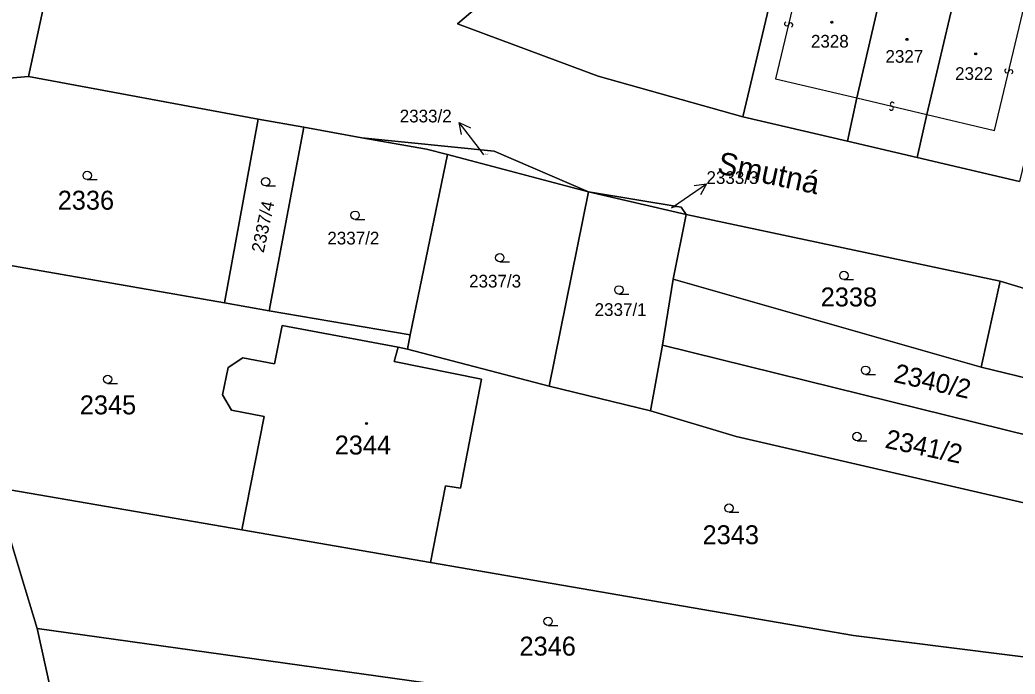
# Model space of a CAD drawing. Extents: x -596024 to -594475, y -1163820 to -1161957.
# Drawn here: x -595927.3 to -595838.1, y -1163093.4 to -1163034.7 of the extents above; entities that cross this region are included whole.
import ezdxf

# ---------------------------------------------------------------- set-up
doc = ezdxf.new("R2010")
doc.units = 0
for name, color, linetype in [('Level 1', 7, 'Continuous'), ('Level 11', 7, 'Continuous'), ('Level 13', 7, 'Continuous'), ('Level 3', 7, 'Continuous'), ('Level 4', 7, 'Continuous'), ('Level 5', 7, 'Continuous'), ('Level 57', 7, 'Continuous'), ('Level 60', 7, 'Continuous')]:
    doc.layers.add(name, color=color, linetype=linetype)

msp = doc.modelspace()

# ---------------------------------------------------------------- linework, layer by layer
at = {"layer": 'Level 1'}
for points in [[(-595857.24, -1163021.24), (-595862.49, -1163043.42)], [(-595862.49, -1163043.42), (-595875.46, -1163039.76), (-595888.08, -1163035.08), (-595884.71, -1163032.18), (-595878.92, -1163030.64), (-595875.37, -1163027.29), (-595874.48, -1163022.93)], [(-595926.56, -1163039.8), (-595922.93, -1163023.02)], [(-595849.55, -1163029.96), (-595849.99, -1163031.89), (-595850.24, -1163032.96), (-595852.27, -1163041.72)], [(-595845.99, -1163043.21), (-595843.96, -1163034.59)], [(-595926.56, -1163039.8), (-595931.74, -1163040.25), (-595934.31, -1163041.39), (-595935.44, -1163043.08)], [(-595926.56, -1163039.8), (-595905.95, -1163043.63)], [(-595853.11, -1163045.6), (-595852.27, -1163041.72)], [(-595862.49, -1163043.42), (-595853.11, -1163045.6)], [(-595846.87, -1163047.06), (-595845.99, -1163043.21)], [(-595905.95, -1163043.63), (-595908.98, -1163060.11)], [(-595901.87, -1163044.35), (-595905.95, -1163043.63)], [(-595904.98, -1163060.8), (-595901.87, -1163044.35)], [(-595896.65, -1163045.28), (-595901.87, -1163044.35)], [(-595896.65, -1163045.28), (-595890.87, -1163046.3), (-595888.96, -1163046.8)], [(-595876.33, -1163050.15), (-595884.8, -1163046.5), (-595896.65, -1163045.28)], [(-595853.11, -1163045.6), (-595846.87, -1163047.06)], [(-595888.96, -1163046.8), (-595892.33, -1163062.97)], [(-595888.96, -1163046.8), (-595876.33, -1163050.15)], [(-595846.87, -1163047.06), (-595837.67, -1163049.21)], [(-595879.85, -1163067.57), (-595876.33, -1163050.15)], [(-595876.33, -1163050.15), (-595867.58, -1163052.17)], [(-595867.58, -1163052.17), (-595868.01, -1163051.5), (-595876.33, -1163050.15)], [(-595867.58, -1163052.17), (-595868.75, -1163057.97)], [(-595867.58, -1163052.17), (-595839.42, -1163058.15)], [(-595908.98, -1163060.11), (-595933.67, -1163055.8)], [(-595868.75, -1163057.97), (-595869.68, -1163063.89)], [(-595841.12, -1163065.86), (-595868.75, -1163057.97)], [(-595839.42, -1163058.15), (-595841.12, -1163065.86)], [(-595779.65, -1163068.86), (-595798.9, -1163066.88), (-595824.16, -1163062.75), (-595839.42, -1163058.15)], [(-595908.98, -1163060.11), (-595904.98, -1163060.8)], [(-595904.98, -1163060.8), (-595892.33, -1163062.97)], [(-595893.4, -1163064.07), (-595903.81, -1163062.12), (-595904.48, -1163065.56), (-595907.34, -1163065.02), (-595908.64, -1163065.9), (-595909.15, -1163068.35), (-595908.34, -1163069.72), (-595905.42, -1163070.28), (-595907.41, -1163080.47)], [(-595892.33, -1163062.97), (-595892.55, -1163064.26)], [(-595870.77, -1163069.78), (-595869.68, -1163063.89)], [(-595869.68, -1163063.89), (-595823.71, -1163075.27)], [(-595890.49, -1163083.39), (-595889.15, -1163076.51), (-595887.81, -1163076.72), (-595885.93, -1163066.94), (-595893.75, -1163065.36), (-595893.4, -1163064.07)], [(-595892.55, -1163064.26), (-595893.4, -1163064.07)], [(-595879.85, -1163067.57), (-595892.55, -1163064.26)], [(-595841.12, -1163065.86), (-595822.9, -1163070.28)], [(-595870.77, -1163069.78), (-595879.85, -1163067.57)], [(-595870.77, -1163069.78), (-595863.08, -1163072.08), (-595832.64, -1163079.12)], [(-595929.12, -1163076.73), (-595929.61, -1163076.65), (-595927.24, -1163084.46), (-595925.78, -1163089.31)], [(-595929.12, -1163076.73), (-595907.41, -1163080.47)], [(-595890.49, -1163083.39), (-595907.41, -1163080.47)], [(-595834.51, -1163092.21), (-595852.58, -1163089.93), (-595890.49, -1163083.39)], [(-595925.78, -1163089.31), (-595924.6, -1163094.59)], [(-595925.78, -1163089.31), (-595852, -1163099.63), (-595840.28, -1163100.69)]]:
    msp.add_lwpolyline(points, dxfattribs=at)
at = {"layer": 'Level 13'}
for centre, start, end in [((-595858.559, -1163035.077), 113.74464, 346.33464), ((-595858.201, -1163035.164), 293.95909, 166.05709), ((-595838.819, -1163039.286), 113.97294, 346.07094), ((-595838.461, -1163039.373), 293.75849, 166.34849), ((-595849.173, -1163042.639), 203.81101, 76.40101), ((-595849.086, -1163042.281), 24.02547, 256.12347)]:
    msp.add_arc(centre, 0.184, start, end, dxfattribs=at)
at = {"layer": 'Level 3'}
for points in [[(-595848.42, -1163025.11), (-595849.44, -1163024.88), (-595849.98, -1163026.98), (-595850.22, -1163026.92), (-595850.79, -1163029.15), (-595852.49, -1163028.72), (-595853.06, -1163031.19), (-595855.87, -1163030.54), (-595857.22, -1163030.23), (-595859.55, -1163040), (-595858.16, -1163040.33), (-595852.27, -1163041.72)], [(-595845.99, -1163043.21), (-595839.91, -1163044.64), (-595837.38, -1163034.02), (-595843.47, -1163032.55)], [(-595852.27, -1163041.72), (-595845.99, -1163043.21)]]:
    msp.add_lwpolyline(points, dxfattribs=at)
at = {"layer": 'Level 5'}
for p, q in [((-595921.28, -1163049.04), (-595920.405, -1163049.04)), ((-595905.28, -1163049.61), (-595904.405, -1163049.61)), ((-595897.26, -1163052.61), (-595896.385, -1163052.61)), ((-595884.29, -1163056.42), (-595883.415, -1163056.42)), ((-595853.43, -1163058.01), (-595852.555, -1163058.01)), ((-595873.6, -1163059.31), (-595872.725, -1163059.31)), ((-595851.48, -1163066.52), (-595850.605, -1163066.52)), ((-595919.45, -1163067.33), (-595918.575, -1163067.33)), ((-595852.25, -1163072.46), (-595851.375, -1163072.46)), ((-595863.73, -1163078.88), (-595862.855, -1163078.88)), ((-595879.95, -1163089.04), (-595879.075, -1163089.04))]:
    msp.add_line(p, q, dxfattribs=at)
for centre, radius in [((-595854.51, -1163034.93), 0.09), ((-595854.51, -1163034.93), 0.0521), ((-595847.77, -1163036.46), 0.09), ((-595847.77, -1163036.46), 0.0521), ((-595841.61, -1163037.77), 0.09), ((-595841.61, -1163037.77), 0.0521), ((-595921.28, -1163048.665), 0.375), ((-595905.28, -1163049.235), 0.375), ((-595897.26, -1163052.235), 0.375), ((-595884.29, -1163056.045), 0.375), ((-595853.43, -1163057.635), 0.375), ((-595873.6, -1163058.935), 0.375), ((-595851.48, -1163066.145), 0.375), ((-595919.45, -1163066.955), 0.375), ((-595896.24, -1163070.92), 0.09), ((-595896.24, -1163070.92), 0.0521), ((-595852.25, -1163072.085), 0.375), ((-595863.73, -1163078.505), 0.375), ((-595879.95, -1163088.665), 0.375)]:
    msp.add_circle(centre, radius, dxfattribs=at)
at = {"layer": 'Level 57'}
for p, q in [((-595886.106, -1163046.292), (-595887.93, -1163043.91)), ((-595885.71, -1163046.81), (-595886.106, -1163046.292)), ((-595868.223, -1163051.129), (-595865.75, -1163049.43)), ((-595868.88, -1163051.58), (-595868.223, -1163051.129))]:
    msp.add_line(p, q, dxfattribs=at)
for points in [[(-595887.719, -1163045.008), (-595887.93, -1163043.91), (-595886.925, -1163044.4)], [(-595866.858, -1163049.584), (-595865.75, -1163049.43), (-595866.291, -1163050.409)]]:
    msp.add_lwpolyline(points, dxfattribs=at)
at = {"layer": 'Level 60'}
for points in [[(-595850.9, -1163019.65), (-595847.13, -1163019.59), (-595847.68, -1163021.94), (-595848.42, -1163025.11), (-595849.55, -1163029.96), (-595849.99, -1163031.89), (-595850.24, -1163032.96), (-595852.27, -1163041.72), (-595853.11, -1163045.6), (-595862.49, -1163043.42), (-595857.24, -1163021.24), (-595856.92, -1163019.88)], [(-595862.49, -1163043.42), (-595875.46, -1163039.76), (-595888.08, -1163035.08), (-595884.71, -1163032.18), (-595878.92, -1163030.64), (-595875.37, -1163027.29), (-595874.48, -1163022.93), (-595857.24, -1163021.24)], [(-595846.87, -1163047.06), (-595845.99, -1163043.21), (-595843.96, -1163034.59), (-595843.47, -1163032.55), (-595843.16, -1163031.19), (-595842.85, -1163029.82), (-595842.7, -1163029.19), (-595842.29, -1163027.35), (-595836.43, -1163028.66), (-595835, -1163029.47), (-595833.37, -1163029.92), (-595833.5, -1163031.99), (-595834.18, -1163034.79), (-595834.6, -1163036.51), (-595837.67, -1163049.21)], [(-595849.55, -1163029.96), (-595848.2, -1163030.19), (-595843.16, -1163031.19), (-595843.47, -1163032.55), (-595843.96, -1163034.59), (-595845.99, -1163043.21), (-595846.87, -1163047.06), (-595853.11, -1163045.6), (-595852.27, -1163041.72), (-595850.24, -1163032.96), (-595849.99, -1163031.89)], [(-595936.27, -1163047.75), (-595935.44, -1163043.08), (-595934.31, -1163041.39), (-595931.74, -1163040.25), (-595926.56, -1163039.8), (-595905.95, -1163043.63), (-595908.98, -1163060.11), (-595933.67, -1163055.8)], [(-595908.98, -1163060.11), (-595905.95, -1163043.63), (-595901.87, -1163044.35), (-595904.98, -1163060.8)], [(-595896.65, -1163045.28), (-595890.87, -1163046.3), (-595888.96, -1163046.8), (-595892.33, -1163062.97), (-595904.98, -1163060.8), (-595901.87, -1163044.35)], [(-595890.87, -1163046.3), (-595896.65, -1163045.28), (-595884.8, -1163046.5), (-595876.33, -1163050.15), (-595888.96, -1163046.8)], [(-595892.55, -1163064.26), (-595892.33, -1163062.97), (-595888.96, -1163046.8), (-595876.33, -1163050.15), (-595879.85, -1163067.57)], [(-595869.68, -1163063.89), (-595870.77, -1163069.78), (-595879.85, -1163067.57), (-595876.33, -1163050.15), (-595867.58, -1163052.17), (-595868.75, -1163057.97)], [(-595868.01, -1163051.5), (-595867.58, -1163052.17), (-595876.33, -1163050.15)], [(-595867.58, -1163052.17), (-595839.42, -1163058.15), (-595841.12, -1163065.86), (-595868.75, -1163057.97)], [(-595892.33, -1163062.97), (-595892.55, -1163064.26), (-595893.4, -1163064.07), (-595903.81, -1163062.12), (-595904.48, -1163065.56), (-595907.34, -1163065.02), (-595908.64, -1163065.9), (-595909.15, -1163068.35), (-595908.34, -1163069.72), (-595905.42, -1163070.28), (-595907.41, -1163080.47), (-595929.12, -1163076.73), (-595933.67, -1163055.8), (-595908.98, -1163060.11), (-595904.98, -1163060.8)], [(-595868.75, -1163057.97), (-595841.12, -1163065.86), (-595822.9, -1163070.28), (-595823.71, -1163075.27), (-595869.68, -1163063.89)], [(-595841.12, -1163065.86), (-595839.42, -1163058.15), (-595824.16, -1163062.75), (-595798.9, -1163066.88), (-595779.65, -1163068.86), (-595780.6, -1163073.68), (-595817.56, -1163071.57), (-595822.9, -1163070.28)], [(-595887.81, -1163076.72), (-595889.15, -1163076.51), (-595890.49, -1163083.39), (-595907.41, -1163080.47), (-595905.42, -1163070.28), (-595908.34, -1163069.72), (-595909.15, -1163068.35), (-595908.64, -1163065.9), (-595907.34, -1163065.02), (-595904.48, -1163065.56), (-595903.81, -1163062.12), (-595893.4, -1163064.07), (-595893.75, -1163065.36), (-595885.93, -1163066.94)], [(-595863.08, -1163072.08), (-595870.77, -1163069.78), (-595869.68, -1163063.89), (-595823.71, -1163075.27), (-595824.57, -1163080.54), (-595832.64, -1163079.12)], [(-595870.77, -1163069.78), (-595863.08, -1163072.08), (-595832.64, -1163079.12), (-595834.51, -1163092.21), (-595852.58, -1163089.93), (-595890.49, -1163083.39), (-595889.15, -1163076.51), (-595887.81, -1163076.72), (-595885.93, -1163066.94), (-595893.75, -1163065.36), (-595893.4, -1163064.07), (-595892.55, -1163064.26), (-595879.85, -1163067.57)], [(-595927.24, -1163084.46), (-595929.61, -1163076.65), (-595929.12, -1163076.73), (-595907.41, -1163080.47), (-595890.49, -1163083.39), (-595852.58, -1163089.93), (-595834.51, -1163092.21), (-595830.15, -1163092.76), (-595831.2, -1163101.51), (-595840.28, -1163100.69), (-595852, -1163099.63), (-595925.78, -1163089.31)], [(-595924.6, -1163094.59), (-595925.78, -1163089.31), (-595852, -1163099.63), (-595840.28, -1163100.69), (-595840.88, -1163104.53), (-595851.75, -1163103.77)]]:
    msp.add_lwpolyline(points, close=True, dxfattribs=at)
for points in [[(-595922.93, -1163023.02), (-595926.56, -1163039.8), (-595931.74, -1163040.25), (-595934.31, -1163041.39), (-595935.44, -1163043.08), (-595944.56, -1163045.07), (-595947.37, -1163040.28), (-595952.5, -1163038.05), (-595953.04, -1163038.1), (-595961.79, -1163038.99), (-595969.6, -1163039.64), (-595978.18, -1163041.03), (-595993.18, -1163043.47), (-596002.48, -1163045.26), (-596002.3, -1163042.9), (-596001.4, -1163037.5), (-596007.9, -1163039.1), (-596011.52, -1163039.43), (-596013.6, -1163037.7), (-596013.91, -1163035.64), (-596013, -1163034.5)], [(-595824.16, -1163062.75), (-595839.42, -1163058.15), (-595867.58, -1163052.17), (-595868.01, -1163051.5), (-595876.33, -1163050.15), (-595884.8, -1163046.5), (-595896.65, -1163045.28), (-595901.87, -1163044.35), (-595905.95, -1163043.63), (-595926.56, -1163039.8), (-595922.93, -1163023.02)], [(-595884.71, -1163032.18), (-595888.08, -1163035.08), (-595875.46, -1163039.76), (-595862.49, -1163043.42), (-595853.11, -1163045.6), (-595846.87, -1163047.06), (-595837.67, -1163049.21)], [(-595929.61, -1163076.65), (-595927.24, -1163084.46), (-595925.78, -1163089.31), (-595924.6, -1163094.59), (-595923.18, -1163100.06), (-595921.21, -1163107.95), (-595921.08, -1163115.67), (-595920.82, -1163123.6), (-595920.75, -1163127.32), (-595920.68, -1163131.15), (-595920.55, -1163134.93), (-595920.42, -1163138.76), (-595920.45, -1163142.03), (-595920.76, -1163145.31), (-595920.39, -1163145.34), (-595920.14, -1163153.9), (-595920.42, -1163161.89)]]:
    msp.add_lwpolyline(points, dxfattribs=at)

# ---------------------------------------------------------------- texts
at = {"layer": 'Level 11'}
msp.add_text('Smutná', height=2, rotation=348.04395, dxfattribs=at).set_placement((-595864.878, -1163048.461))
at = {"layer": 'Level 4'}
for s, height, p in [('2328', 1.14, (-595856.385, -1163037.2)), ('2327', 1.14, (-595849.7, -1163038.56)), ('2322', 1.14, (-595843.456, -1163040.1)), ('2333/2', 0.1, (-595885.71, -1163046.81)), ('2336', 1.7, (-595923.931, -1163051.74)), ('2333/3', 0.1, (-595868.88, -1163051.58)), ('2337/2', 1.14, (-595899.75, -1163054.86)), ('2337/3', 1.14, (-595887.038, -1163058.72)), ('2338', 1.7, (-595855.509, -1163060.42)), ('2337/1', 1.14, (-595875.782, -1163061.27)), ('2345', 1.7, (-595921.95, -1163070.1)), ('2344', 1.7, (-595899.09, -1163073.7)), ('2343', 1.7, (-595866.1, -1163081.75)), ('2346', 1.7, (-595882.52, -1163091.74))]:
    msp.add_text(s, height=height, dxfattribs=at).set_placement(p)
for s, height, rotation, p in [('2337/4', 1.14, 77.98851, (-595905.46, -1163055.661)), ('2340/2', 1.7, 347.25618, (-595849.05, -1163067.18)), ('2341/2', 1.7, 347.99382, (-595849.82, -1163073.08))]:
    msp.add_text(s, height=height, rotation=rotation, dxfattribs=at).set_placement(p)
at = {"layer": 'Level 57'}
for s, p in [('2333/2', (-595893.26, -1163043.91)), ('2333/3', (-595865.75, -1163049.43))]:
    msp.add_text(s, height=1.14, dxfattribs=at).set_placement(p)

doc.saveas('drawing.dxf')
